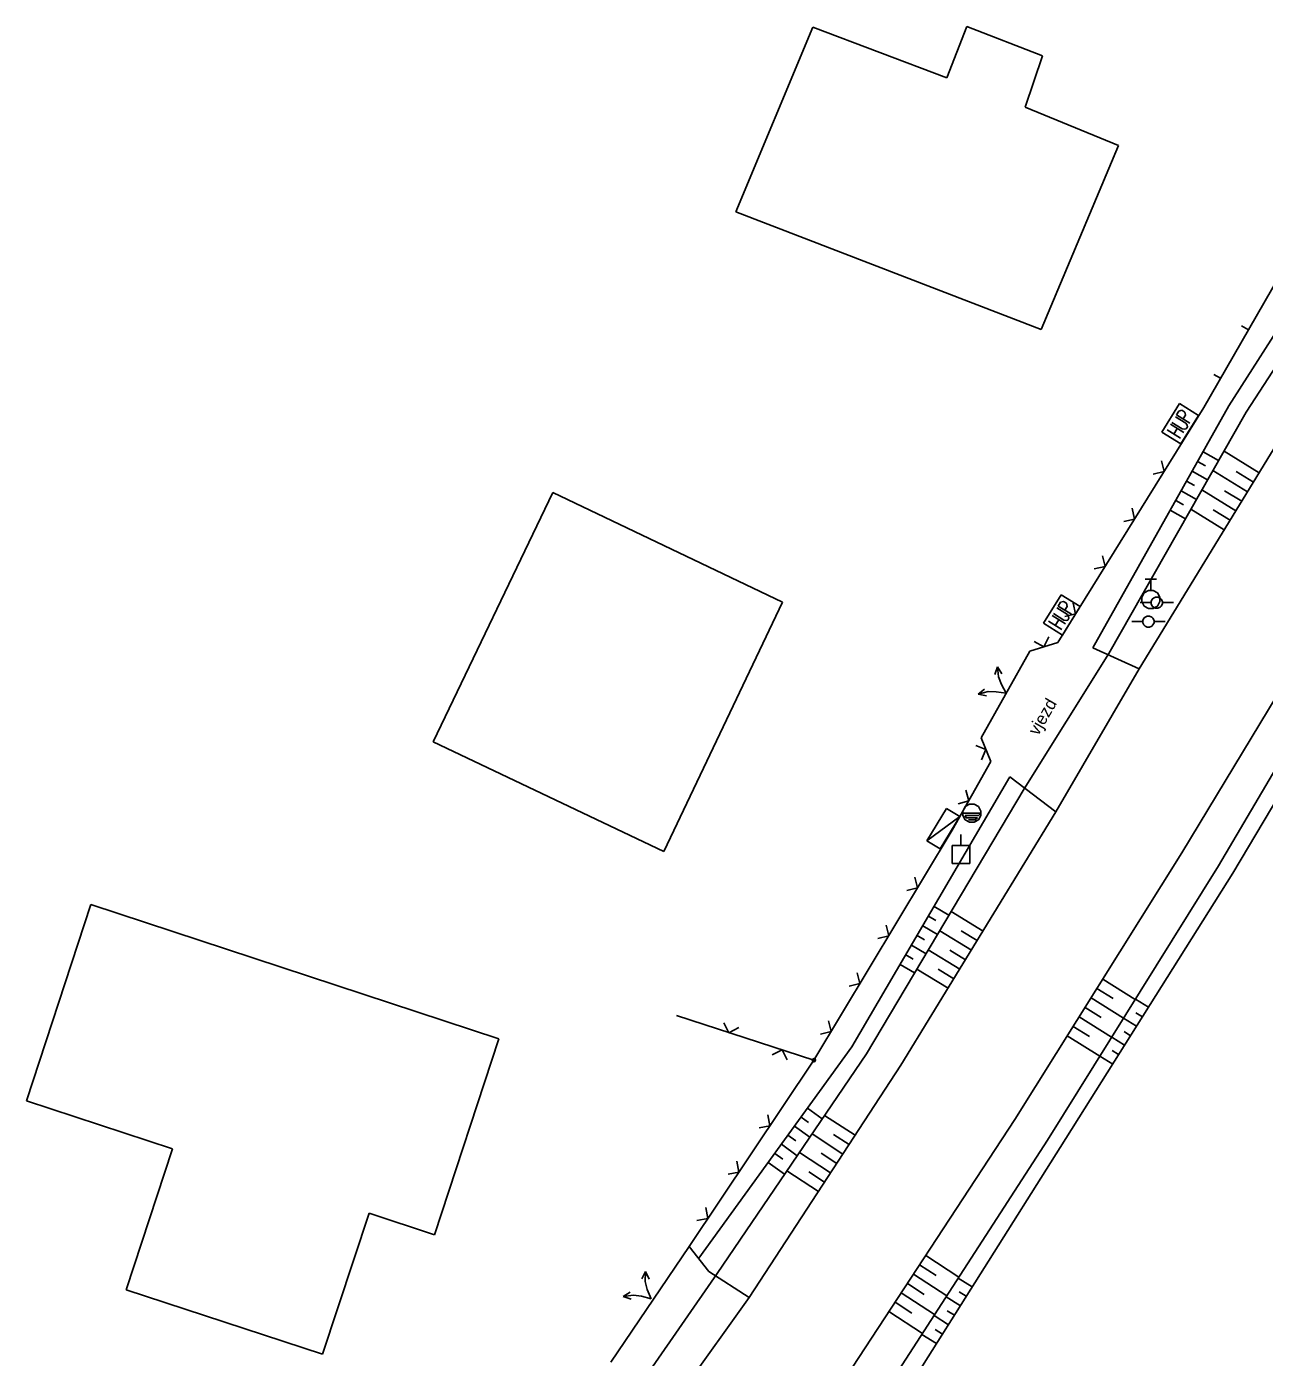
# Model space of a CAD drawing. Extents: x -559554 to -559082, y -1075950 to -1075150.
# Drawn here: x -559537.9 to -559482.5, y -1075896 to -1075836.4 of the extents above; entities that cross this region are included whole.
import ezdxf

# ---------------------------------------------------------------- set-up
doc = ezdxf.new("R2010")
doc.units = 0
doc.layers.add('kl', color=7, linetype='Continuous')
doc.layers.add('PF', color=7, linetype='Continuous')

msp = doc.modelspace()

# ---------------------------------------------------------------- linework, layer by layer
at = {"layer": 'kl'}
for p, q in [((-559485.169, -1075853.462), (-559480.41, -1075845.17)), ((-559479.439, -1075846.158), (-559484.05, -1075853.393)), ((-559483.285, -1075853.685), (-559478.597, -1075846.444)), ((-559483.178, -1075849.993), (-559483.482, -1075849.818)), ((-559484.423, -1075852.161), (-559484.726, -1075851.987)), ((-559491.707, -1075863.981), (-559485.169, -1075853.462)), ((-559484.05, -1075853.393), (-559490.145, -1075864.225)), ((-559487.052, -1075854.567), (-559486.26, -1075853.293)), ((-559486.26, -1075853.293), (-559485.41, -1075853.821)), ((-559489.422, -1075864.483), (-559483.285, -1075853.685)), ((-559485.982, -1075854.172), (-559486.449, -1075853.882)), ((-559486.396, -1075853.797), (-559486.291, -1075853.627)), ((-559485.802, -1075854.166), (-559486.396, -1075853.797)), ((-559486.291, -1075853.627), (-559486.153, -1075853.595)), ((-559485.41, -1075853.821), (-559486.202, -1075855.095)), ((-559486.153, -1075853.595), (-559486.026, -1075853.674)), ((-559485.993, -1075853.812), (-559486.099, -1075853.981)), ((-559486.026, -1075853.674), (-559485.993, -1075853.812)), ((-559481.408, -1075854.294), (-559488.075, -1075865.172)), ((-559486.202, -1075855.095), (-559487.052, -1075854.567)), ((-559486.819, -1075854.476), (-559486.224, -1075854.846)), ((-559486.066, -1075854.591), (-559486.66, -1075854.221)), ((-559486.607, -1075854.136), (-559486.14, -1075854.427)), ((-559486.521, -1075854.661), (-559486.363, -1075854.406)), ((-559486.14, -1075854.427), (-559486.029, -1075854.437)), ((-559486.029, -1075854.437), (-559485.96, -1075854.421)), ((-559485.923, -1075854.267), (-559485.982, -1075854.172)), ((-559485.96, -1075854.421), (-559485.907, -1075854.336)), ((-559485.907, -1075854.336), (-559485.923, -1075854.267)), ((-559486.956, -1075856.337), (-559487.069, -1075855.855)), ((-559485.454, -1075855.887), (-559485.106, -1075856.083)), ((-559485.209, -1075855.451), (-559484.512, -1075855.843)), ((-559482.69, -1075856.386), (-559484.27, -1075855.418)), ((-559487.438, -1075856.449), (-559486.956, -1075856.337)), ((-559486.154, -1075873.396), (-559475.803, -1075856.248)), ((-559485.699, -1075856.323), (-559485.006, -1075856.713)), ((-559483.213, -1075857.238), (-559484.764, -1075856.288)), ((-559482.951, -1075856.812), (-559483.734, -1075856.332)), ((-559485.944, -1075856.759), (-559485.598, -1075856.953)), ((-559474.523, -1075856.978), (-559484.518, -1075873.983)), ((-559486.434, -1075857.63), (-559486.091, -1075857.824)), ((-559486.189, -1075857.194), (-559485.5, -1075857.582)), ((-559483.735, -1075858.091), (-559485.258, -1075857.157)), ((-559483.474, -1075857.665), (-559484.242, -1075857.194)), ((-559473.759, -1075857.239), (-559483.876, -1075874.315)), ((-559488.276, -1075858.46), (-559488.388, -1075857.978)), ((-559486.68, -1075858.066), (-559485.994, -1075858.452)), ((-559484.258, -1075858.944), (-559485.753, -1075858.027)), ((-559483.996, -1075858.517), (-559484.751, -1075858.055)), ((-559488.758, -1075858.573), (-559488.276, -1075858.46)), ((-559490.078, -1075860.696), (-559489.596, -1075860.584)), ((-559489.596, -1075860.584), (-559489.708, -1075860.102)), ((-559487.794, -1075861.16), (-559487.294, -1075861.16)), ((-559487.544, -1075861.66), (-559487.544, -1075861.16)), ((-559492.354, -1075863.127), (-559491.562, -1075861.853)), ((-559491.562, -1075861.853), (-559490.713, -1075862.381)), ((-559487.944, -1075861.96), (-559487.844, -1075861.76)), ((-559487.844, -1075861.76), (-559487.644, -1075861.66)), ((-559487.644, -1075861.66), (-559487.444, -1075861.66)), ((-559487.444, -1075861.66), (-559487.244, -1075861.76)), ((-559487.244, -1075861.76), (-559487.144, -1075861.96)), ((-559491.284, -1075862.732), (-559491.751, -1075862.442)), ((-559491.699, -1075862.357), (-559491.593, -1075862.187)), ((-559491.104, -1075862.727), (-559491.699, -1075862.357)), ((-559491.593, -1075862.187), (-559491.455, -1075862.155)), ((-559490.713, -1075862.381), (-559491.505, -1075863.655)), ((-559491.455, -1075862.155), (-559491.328, -1075862.234)), ((-559491.296, -1075862.372), (-559491.401, -1075862.542)), ((-559491.328, -1075862.234), (-559491.296, -1075862.372)), ((-559490.915, -1075862.707), (-559491.028, -1075862.225)), ((-559488.031, -1075862.205), (-559487.531, -1075862.205)), ((-559487.944, -1075862.16), (-559487.944, -1075861.96)), ((-559487.844, -1075862.36), (-559487.944, -1075862.16)), ((-559487.644, -1075862.46), (-559487.844, -1075862.36)), ((-559487.444, -1075862.46), (-559487.644, -1075862.46)), ((-559487.531, -1075862.155), (-559487.481, -1075862.055)), ((-559487.531, -1075862.255), (-559487.531, -1075862.155)), ((-559487.481, -1075862.355), (-559487.531, -1075862.255)), ((-559487.481, -1075862.055), (-559487.431, -1075862.005)), ((-559487.431, -1075862.405), (-559487.481, -1075862.355)), ((-559487.244, -1075862.36), (-559487.444, -1075862.46)), ((-559487.431, -1075862.005), (-559487.331, -1075861.955)), ((-559487.331, -1075862.455), (-559487.431, -1075862.405)), ((-559487.331, -1075861.955), (-559487.231, -1075861.955)), ((-559487.231, -1075862.455), (-559487.331, -1075862.455)), ((-559487.144, -1075862.16), (-559487.244, -1075862.36)), ((-559487.231, -1075861.955), (-559487.131, -1075862.005)), ((-559487.131, -1075862.405), (-559487.231, -1075862.455)), ((-559487.144, -1075861.96), (-559487.144, -1075862.16)), ((-559487.131, -1075862.005), (-559487.081, -1075862.055)), ((-559487.081, -1075862.355), (-559487.131, -1075862.405)), ((-559487.081, -1075862.055), (-559487.031, -1075862.155)), ((-559487.031, -1075862.255), (-559487.081, -1075862.355)), ((-559487.031, -1075862.155), (-559487.031, -1075862.255)), ((-559487.031, -1075862.205), (-559486.531, -1075862.205)), ((-559492.121, -1075863.037), (-559491.526, -1075863.406)), ((-559491.368, -1075863.151), (-559491.963, -1075862.782)), ((-559491.91, -1075862.697), (-559491.443, -1075862.987)), ((-559491.824, -1075863.221), (-559491.665, -1075862.967)), ((-559491.443, -1075862.987), (-559491.331, -1075862.998)), ((-559491.397, -1075862.819), (-559490.915, -1075862.707)), ((-559491.331, -1075862.998), (-559491.263, -1075862.982)), ((-559491.226, -1075862.828), (-559491.284, -1075862.732)), ((-559491.263, -1075862.982), (-559491.21, -1075862.897)), ((-559491.21, -1075862.897), (-559491.226, -1075862.828)), ((-559488.404, -1075863.054), (-559487.904, -1075863.054)), ((-559487.904, -1075863.004), (-559487.854, -1075862.904)), ((-559487.904, -1075863.104), (-559487.904, -1075863.004)), ((-559487.854, -1075862.904), (-559487.804, -1075862.854)), ((-559487.804, -1075862.854), (-559487.704, -1075862.804)), ((-559487.704, -1075862.804), (-559487.604, -1075862.804)), ((-559487.604, -1075862.804), (-559487.504, -1075862.854)), ((-559487.504, -1075862.854), (-559487.454, -1075862.904)), ((-559487.454, -1075862.904), (-559487.404, -1075863.004)), ((-559487.404, -1075863.004), (-559487.404, -1075863.104)), ((-559487.404, -1075863.054), (-559486.904, -1075863.054)), ((-559491.505, -1075863.655), (-559492.354, -1075863.127)), ((-559487.854, -1075863.204), (-559487.904, -1075863.104)), ((-559487.804, -1075863.254), (-559487.854, -1075863.204)), ((-559487.704, -1075863.304), (-559487.804, -1075863.254)), ((-559487.604, -1075863.304), (-559487.704, -1075863.304)), ((-559487.504, -1075863.254), (-559487.604, -1075863.304)), ((-559487.454, -1075863.204), (-559487.504, -1075863.254)), ((-559487.404, -1075863.104), (-559487.454, -1075863.204)), ((-559492.961, -1075864.374), (-559491.707, -1075863.981)), ((-559492.773, -1075863.948), (-559492.334, -1075864.177)), ((-559492.334, -1075864.177), (-559492.105, -1075863.739)), ((-559488.075, -1075865.172), (-559490.145, -1075864.225)), ((-559495.148, -1075868.257), (-559492.961, -1075864.374)), ((-559493.211, -1075870.538), (-559489.422, -1075864.483)), ((-559494.414, -1075865.07), (-559494.532, -1075865.414)), ((-559494.367, -1075865.529), (-559494.414, -1075865.07)), ((-559494.414, -1075865.07), (-559494.212, -1075865.393)), ((-559488.075, -1075865.172), (-559491.794, -1075871.572)), ((-559494.236, -1075865.864), (-559494.367, -1075865.529)), ((-559494.022, -1075866.257), (-559494.236, -1075865.864)), ((-559495.271, -1075866.301), (-559494.989, -1075866.071)), ((-559495.271, -1075866.301), (-559494.825, -1075866.185)), ((-559495.271, -1075866.301), (-559494.898, -1075866.378)), ((-559494.825, -1075866.185), (-559494.464, -1075866.192)), ((-559494.464, -1075866.192), (-559494.022, -1075866.257)), ((-559495.148, -1075868.257), (-559494.71, -1075869.314)), ((-559494.929, -1075868.785), (-559495.386, -1075868.596)), ((-559495.119, -1075869.243), (-559494.929, -1075868.785)), ((-559496.436, -1075872.382), (-559494.71, -1075869.314)), ((-559493.855, -1075870.007), (-559500.924, -1075882.092)), ((-559491.794, -1075871.572), (-559493.855, -1075870.007)), ((-559500.281, -1075882.401), (-559493.211, -1075870.538)), ((-559495.7, -1075871.075), (-559495.834, -1075870.598)), ((-559496.177, -1075871.208), (-559495.7, -1075871.075)), ((-559495.961, -1075871.531), (-559495.861, -1075871.331)), ((-559495.861, -1075871.331), (-559495.661, -1075871.231)), ((-559495.661, -1075871.231), (-559495.461, -1075871.231)), ((-559495.461, -1075871.231), (-559495.261, -1075871.331)), ((-559495.261, -1075871.331), (-559495.161, -1075871.531)), ((-559491.794, -1075871.572), (-559498.73, -1075882.908)), ((-559497.569, -1075872.87), (-559496.693, -1075871.413)), ((-559497.569, -1075872.87), (-559496.093, -1075871.774)), ((-559496.093, -1075871.774), (-559496.969, -1075873.231)), ((-559496.693, -1075871.413), (-559496.093, -1075871.774)), ((-559495.961, -1075871.731), (-559495.961, -1075871.531)), ((-559495.961, -1075871.631), (-559495.161, -1075871.631)), ((-559495.861, -1075871.931), (-559495.961, -1075871.731)), ((-559495.261, -1075871.731), (-559495.861, -1075871.731)), ((-559495.861, -1075871.731), (-559495.811, -1075871.831)), ((-559495.661, -1075872.031), (-559495.861, -1075871.931)), ((-559495.811, -1075871.831), (-559495.311, -1075871.831)), ((-559495.411, -1075871.931), (-559495.711, -1075871.931)), ((-559495.261, -1075871.931), (-559495.461, -1075872.031)), ((-559495.311, -1075871.831), (-559495.411, -1075871.931)), ((-559495.161, -1075871.631), (-559495.261, -1075871.731)), ((-559495.161, -1075871.731), (-559495.261, -1075871.931)), ((-559495.161, -1075871.531), (-559495.161, -1075871.731)), ((-559502.628, -1075882.686), (-559496.436, -1075872.382)), ((-559496.045, -1075873.079), (-559496.045, -1075872.579)), ((-559495.461, -1075872.031), (-559495.661, -1075872.031)), ((-559496.969, -1075873.231), (-559497.569, -1075872.87)), ((-559496.445, -1075873.079), (-559495.645, -1075873.079)), ((-559496.445, -1075873.879), (-559496.445, -1075873.079)), ((-559495.645, -1075873.079), (-559495.645, -1075873.879)), ((-559493.631, -1075885.343), (-559486.154, -1075873.396)), ((-559495.645, -1075873.879), (-559496.445, -1075873.879)), ((-559484.518, -1075873.983), (-559492.171, -1075886.266)), ((-559483.876, -1075874.315), (-559491.607, -1075886.596)), ((-559498.472, -1075875.092), (-559497.992, -1075874.972)), ((-559497.992, -1075874.972), (-559498.112, -1075874.492)), ((-559497.25, -1075875.81), (-559496.585, -1075876.199)), ((-559495.058, -1075876.906), (-559496.486, -1075876.033)), ((-559499.28, -1075877.115), (-559499.4, -1075876.635)), ((-559497.755, -1075876.673), (-559497.097, -1075877.058)), ((-559497.502, -1075876.242), (-559497.172, -1075876.435)), ((-559499.76, -1075877.235), (-559499.28, -1075877.115)), ((-559498.007, -1075877.105), (-559497.68, -1075877.296)), ((-559495.58, -1075877.759), (-559496.998, -1075876.892)), ((-559495.319, -1075877.333), (-559496.03, -1075876.898)), ((-559498.26, -1075877.537), (-559497.609, -1075877.917)), ((-559496.102, -1075878.612), (-559497.51, -1075877.751)), ((-559495.841, -1075878.186), (-559496.547, -1075877.754)), ((-559498.765, -1075878.4), (-559498.121, -1075878.776)), ((-559498.512, -1075877.968), (-559498.188, -1075878.158)), ((-559500.568, -1075879.258), (-559500.687, -1075878.778)), ((-559496.624, -1075879.465), (-559498.022, -1075878.61)), ((-559496.363, -1075879.039), (-559497.064, -1075878.61)), ((-559489.694, -1075879.053), (-559488.243, -1075879.961)), ((-559501.048, -1075879.377), (-559500.568, -1075879.258)), ((-559489.959, -1075879.476), (-559489.233, -1075879.931)), ((-559490.49, -1075880.324), (-559489.763, -1075880.779)), ((-559490.224, -1075879.9), (-559488.772, -1075880.81)), ((-559487.656, -1075880.319), (-559488.238, -1075879.953)), ((-559502.628, -1075882.686), (-559508.786, -1075880.69)), ((-559501.856, -1075881.401), (-559501.975, -1075880.92)), ((-559490.755, -1075880.748), (-559489.3, -1075881.658)), ((-559488.188, -1075881.165), (-559488.767, -1075880.802)), ((-559487.922, -1075880.742), (-559488.212, -1075880.56)), ((-559506.658, -1075881.012), (-559506.433, -1075881.453)), ((-559506.433, -1075881.453), (-559505.992, -1075881.228)), ((-559502.336, -1075881.52), (-559501.856, -1075881.401)), ((-559491.02, -1075881.172), (-559490.292, -1075881.627)), ((-559488.455, -1075881.589), (-559488.743, -1075881.407)), ((-559500.924, -1075882.092), (-559507.784, -1075891.554)), ((-559491.285, -1075881.596), (-559489.829, -1075882.507)), ((-559488.721, -1075882.012), (-559489.295, -1075881.65)), ((-559508.213, -1075891.018), (-559502.628, -1075882.686)), ((-559506.954, -1075892.239), (-559500.281, -1075882.401)), ((-559504.055, -1075882.224), (-559504.496, -1075882.449)), ((-559503.83, -1075882.665), (-559504.055, -1075882.224)), ((-559502.678, -1075882.661), (-559502.678, -1075882.712)), ((-559502.678, -1075882.712), (-559502.653, -1075882.737)), ((-559502.653, -1075882.737), (-559502.653, -1075882.637)), ((-559502.653, -1075882.637), (-559502.628, -1075882.637)), ((-559502.628, -1075882.637), (-559502.628, -1075882.737)), ((-559502.603, -1075882.737), (-559502.603, -1075882.637)), ((-559502.603, -1075882.637), (-559502.578, -1075882.662)), ((-559502.578, -1075882.662), (-559502.578, -1075882.712)), ((-559489.254, -1075882.858), (-559489.824, -1075882.499)), ((-559488.988, -1075882.435), (-559489.274, -1075882.255)), ((-559498.73, -1075882.908), (-559505.531, -1075893.306)), ((-559502.628, -1075882.737), (-559502.603, -1075882.737)), ((-559502.91, -1075884.831), (-559502.252, -1075885.307)), ((-559505.079, -1075885.714), (-559504.594, -1075885.618)), ((-559504.594, -1075885.618), (-559504.689, -1075885.133)), ((-559503.686, -1075900.655), (-559493.631, -1075885.343)), ((-559503.497, -1075885.64), (-559502.814, -1075886.135)), ((-559503.203, -1075885.235), (-559502.868, -1075885.478)), ((-559500.784, -1075886.048), (-559502.149, -1075885.155)), ((-559503.79, -1075886.045), (-559503.443, -1075886.297)), ((-559501.331, -1075886.885), (-559502.711, -1075885.983)), ((-559492.171, -1075886.266), (-559502.089, -1075901.597)), ((-559501.057, -1075886.466), (-559501.744, -1075886.018)), ((-559504.377, -1075886.855), (-559504.017, -1075887.116)), ((-559504.084, -1075886.45), (-559503.376, -1075886.963)), ((-559501.878, -1075887.722), (-559503.272, -1075886.81)), ((-559501.605, -1075887.303), (-559502.298, -1075886.85)), ((-559491.607, -1075886.596), (-559501.447, -1075902.203)), ((-559505.985, -1075887.695), (-559506.081, -1075887.21)), ((-559504.671, -1075887.259), (-559503.937, -1075887.791)), ((-559506.471, -1075887.791), (-559505.985, -1075887.695)), ((-559502.426, -1075888.559), (-559503.834, -1075887.638)), ((-559502.152, -1075888.14), (-559502.852, -1075887.682)), ((-559507.863, -1075889.868), (-559507.377, -1075889.772)), ((-559507.377, -1075889.772), (-559507.473, -1075889.286)), ((-559508.213, -1075891.018), (-559511.717, -1075896.202)), ((-559507.324, -1075892.139), (-559508.213, -1075891.018)), ((-559497.623, -1075891.422), (-559496.137, -1075892.397)), ((-559510.172, -1075892.137), (-559510.328, -1075892.466)), ((-559510.178, -1075892.598), (-559510.172, -1075892.137)), ((-559510.172, -1075892.137), (-559510.009, -1075892.481)), ((-559509.99, -1075896.598), (-559506.954, -1075892.239)), ((-559505.531, -1075893.306), (-559507.324, -1075892.139)), ((-559497.897, -1075891.84), (-559497.153, -1075892.328)), ((-559510.085, -1075892.946), (-559510.178, -1075892.598)), ((-559498.446, -1075892.675), (-559497.699, -1075893.166)), ((-559498.171, -1075892.257), (-559496.68, -1075893.237)), ((-559495.539, -1075892.833), (-559496.164, -1075892.438)), ((-559511.164, -1075893.263), (-559510.857, -1075893.066)), ((-559511.164, -1075893.263), (-559510.707, -1075893.198)), ((-559511.164, -1075893.263), (-559510.802, -1075893.381)), ((-559510.707, -1075893.198), (-559510.35, -1075893.246)), ((-559510.35, -1075893.246), (-559509.917, -1075893.361)), ((-559509.917, -1075893.361), (-559510.085, -1075892.946)), ((-559505.531, -1075893.306), (-559508.543, -1075897.528)), ((-559498.72, -1075893.093), (-559497.224, -1075894.076)), ((-559496.072, -1075893.678), (-559496.707, -1075893.278)), ((-559495.806, -1075893.255), (-559496.121, -1075893.057)), ((-559499.269, -1075893.929), (-559497.767, -1075894.916)), ((-559498.995, -1075893.511), (-559498.245, -1075894.004)), ((-559496.339, -1075894.101), (-559496.659, -1075893.9)), ((-559496.606, -1075894.524), (-559497.25, -1075894.118)), ((-559497.139, -1075895.37), (-559497.794, -1075894.957)), ((-559496.872, -1075894.947), (-559497.197, -1075894.742))]:
    msp.add_line(p, q, dxfattribs=at)
msp.add_circle((-559502.629, -1075882.687), 0.075, dxfattribs=at)
at = {"layer": 'PF'}
for p, q in [((-559502.669, -1075836.439), (-559506.13, -1075844.709)), ((-559496.68, -1075838.709), (-559502.669, -1075836.439)), ((-559495.789, -1075836.419), (-559496.68, -1075838.709)), ((-559495.789, -1075836.419), (-559492.389, -1075837.729)), ((-559492.389, -1075837.729), (-559493.177, -1075840.031)), ((-559493.177, -1075840.031), (-559488.999, -1075841.744)), ((-559488.999, -1075841.744), (-559492.45, -1075849.98)), ((-559506.13, -1075844.709), (-559492.45, -1075849.98)), ((-559514.32, -1075857.27), (-559519.669, -1075868.439)), ((-559514.32, -1075857.27), (-559504.03, -1075862.18)), ((-559504.03, -1075862.18), (-559509.35, -1075873.349)), ((-559509.35, -1075873.349), (-559519.669, -1075868.439)), ((-559535, -1075875.709), (-559537.869, -1075884.499)), ((-559535, -1075875.709), (-559516.729, -1075881.729)), ((-559516.729, -1075881.729), (-559519.609, -1075890.5)), ((-559531.339, -1075886.649), (-559537.869, -1075884.499)), ((-559531.339, -1075886.649), (-559533.409, -1075892.959)), ((-559522.54, -1075889.539), (-559524.629, -1075895.849)), ((-559519.609, -1075890.5), (-559522.54, -1075889.539)), ((-559533.409, -1075892.959), (-559524.629, -1075895.849))]:
    msp.add_line(p, q, dxfattribs=at)

# ---------------------------------------------------------------- texts
at = {"layer": 'kl'}
msp.add_text('vjezd', height=0.5525, rotation=59.83708, dxfattribs=at).set_placement((-559492.598, -1075868.193))

doc.saveas('drawing.dxf')
